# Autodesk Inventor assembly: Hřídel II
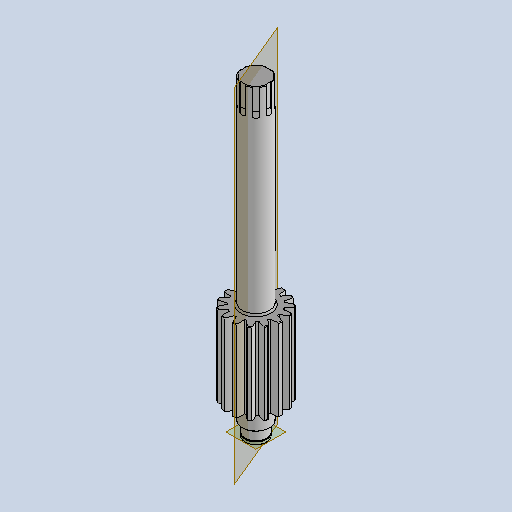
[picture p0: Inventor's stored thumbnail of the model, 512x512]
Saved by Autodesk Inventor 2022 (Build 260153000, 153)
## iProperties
Created: 2025-05
Part Number: Hřídel II
Document SubType Name: Assembly
Designer: jbart
Mass: 1756.11 g
Surface Area: 1642.31 cm^2
Volume: 1756.11 cm^3
Density: 1 g/cm^3
Author: jbart
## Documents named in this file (2)
- C:\Users\jbart\OneDrive\Dokumenty\Inventor\Převodovka navijáku\Hřídel II.iam
- C:\Users\jbart\OneDrive\Dokumenty\Inventor\Převodovka navijáku\Hřídel II\Design Accelerator\Čelní ozubená kola1.iam
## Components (1 placed, 1 different names)
1. Čelní ozubená kola:1 [sub-assembly] — Proti sobě:1, Úhel:1
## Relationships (2: Mate 1, Angle 1)
- Proti sobě:1 [Mate]: Čelní ozubená kola:1
- Úhel:1 [Angle]: Čelní ozubená kola:1
